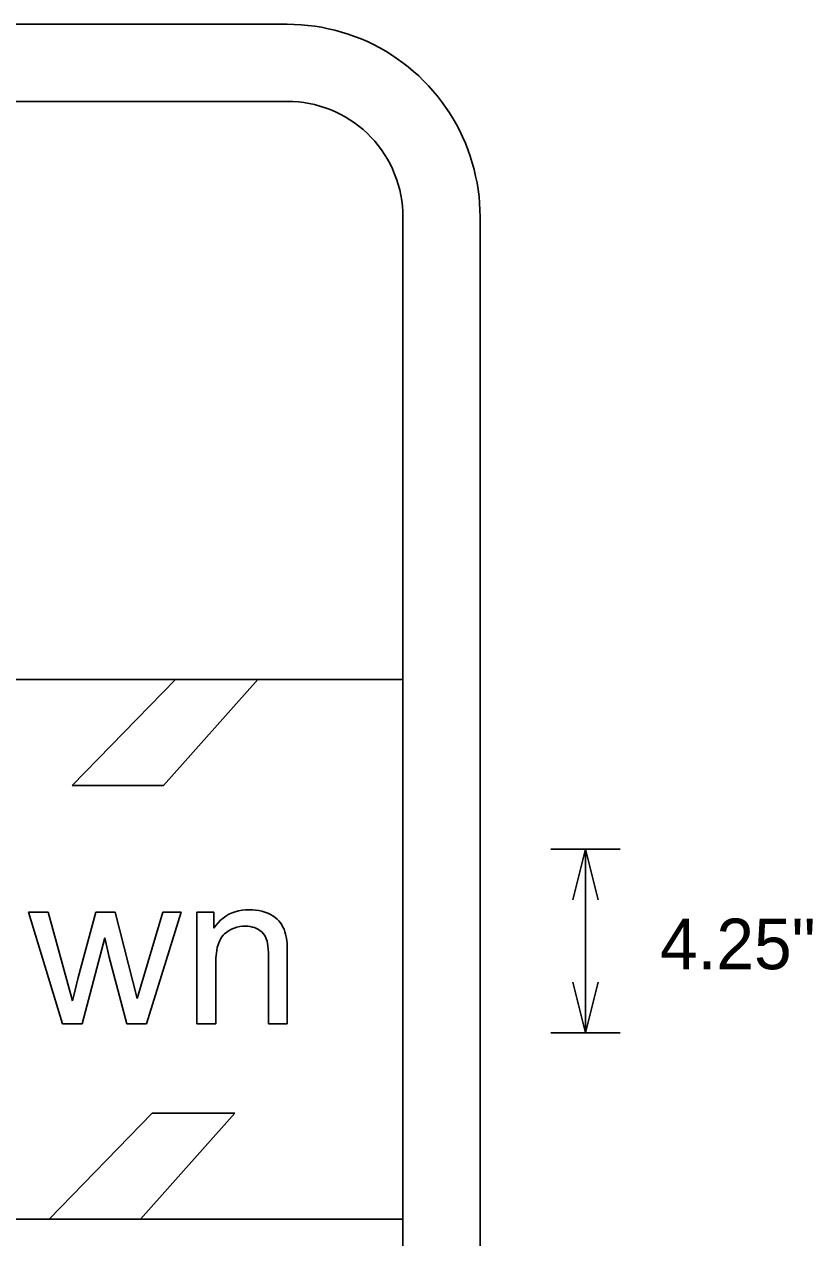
# Model space of a CAD drawing. Extents: x -2842 to 2681, y -2139 to 474.
# Drawn here: x 1523.1 to 1609.4, y -1691.3 to -1558.5 of the extents above; entities that cross this region are included whole.
import ezdxf

# ---------------------------------------------------------------- set-up
doc = ezdxf.new("R2010")
doc.units = 0
doc.layers.add('Default', color=7, linetype='Continuous')

msp = doc.modelspace()

# ---------------------------------------------------------------- linework, layer by layer
at = {"layer": 'Default'}
for p, q in [((1551.91, -1558.48), (1370.51, -1558.48)), ((1552.67, -1558.49), (1551.91, -1558.48)), ((1553.42, -1558.53), (1552.67, -1558.49)), ((1554.17, -1558.6), (1553.42, -1558.53)), ((1554.92, -1558.69), (1554.17, -1558.6)), ((1555.66, -1558.81), (1554.92, -1558.69)), ((1556.4, -1558.96), (1555.66, -1558.81)), ((1557.13, -1559.13), (1556.4, -1558.96)), ((1557.86, -1559.33), (1557.13, -1559.13)), ((1558.57, -1559.56), (1557.86, -1559.33)), ((1559.28, -1559.81), (1558.57, -1559.56)), ((1559.99, -1560.08), (1559.28, -1559.81)), ((1560.68, -1560.38), (1559.99, -1560.08)), ((1561.36, -1560.71), (1560.68, -1560.38)), ((1562.02, -1561.06), (1561.36, -1560.71)), ((1562.68, -1561.43), (1562.02, -1561.06)), ((1563.32, -1561.83), (1562.68, -1561.43)), ((1563.94, -1562.25), (1563.32, -1561.83)), ((1564.55, -1562.69), (1563.94, -1562.25)), ((1565.15, -1563.15), (1564.55, -1562.69)), ((1565.73, -1563.63), (1565.15, -1563.15)), ((1566.29, -1564.13), (1565.73, -1563.63)), ((1566.83, -1564.66), (1566.29, -1564.13)), ((1567.35, -1565.2), (1566.83, -1564.66)), ((1567.85, -1565.76), (1567.35, -1565.2)), ((1568.34, -1566.34), (1567.85, -1565.76)), ((1189.1, -1566.92), (1551.91, -1566.92)), ((1551.91, -1566.92), (1552.52, -1566.93)), ((1552.52, -1566.93), (1553.12, -1566.97)), ((1553.12, -1566.97), (1553.71, -1567.04)), ((1553.71, -1567.04), (1554.31, -1567.14)), ((1568.8, -1566.93), (1568.34, -1566.34)), ((1569.24, -1567.54), (1568.8, -1566.93)), ((1554.31, -1567.14), (1554.9, -1567.27)), ((1554.9, -1567.27), (1555.48, -1567.43)), ((1555.48, -1567.43), (1556.05, -1567.61)), ((1556.05, -1567.61), (1556.62, -1567.82)), ((1556.62, -1567.82), (1557.17, -1568.06)), ((1557.17, -1568.06), (1557.71, -1568.32)), ((1557.71, -1568.32), (1558.24, -1568.61)), ((1569.66, -1568.17), (1569.24, -1567.54)), ((1570.05, -1568.81), (1569.66, -1568.17)), ((1558.24, -1568.61), (1558.76, -1568.92)), ((1558.76, -1568.92), (1559.25, -1569.26)), ((1559.25, -1569.26), (1559.74, -1569.62)), ((1559.74, -1569.62), (1560.2, -1570.01)), ((1570.43, -1569.46), (1570.05, -1568.81)), ((1570.78, -1570.13), (1570.43, -1569.46)), ((1560.2, -1570.01), (1560.65, -1570.41)), ((1560.65, -1570.41), (1561.07, -1570.84)), ((1561.07, -1570.84), (1561.48, -1571.28)), ((1571.1, -1570.81), (1570.78, -1570.13)), ((1571.4, -1571.5), (1571.1, -1570.81)), ((1561.48, -1571.28), (1561.86, -1571.75)), ((1561.86, -1571.75), (1562.22, -1572.23)), ((1562.22, -1572.23), (1562.56, -1572.73)), ((1571.68, -1572.2), (1571.4, -1571.5)), ((1571.93, -1572.91), (1571.68, -1572.2)), ((1562.56, -1572.73), (1562.87, -1573.24)), ((1562.87, -1573.24), (1563.16, -1573.77)), ((1572.15, -1573.63), (1571.93, -1572.91)), ((1572.35, -1574.36), (1572.15, -1573.63)), ((1563.16, -1573.77), (1563.43, -1574.31)), ((1563.43, -1574.31), (1563.66, -1574.87)), ((1563.66, -1574.87), (1563.87, -1575.43)), ((1572.52, -1575.09), (1572.35, -1574.36)), ((1572.67, -1575.83), (1572.52, -1575.09)), ((1563.87, -1575.43), (1564.06, -1576.01)), ((1564.06, -1576.01), (1564.21, -1576.59)), ((1572.79, -1576.57), (1572.67, -1575.83)), ((1564.21, -1576.59), (1564.34, -1577.18)), ((1564.34, -1577.18), (1564.44, -1577.77)), ((1572.89, -1577.32), (1572.79, -1576.57)), ((1572.95, -1578.07), (1572.89, -1577.32)), ((1564.44, -1577.77), (1564.51, -1578.37)), ((1564.51, -1578.37), (1564.56, -1578.97)), ((1564.56, -1578.97), (1564.57, -1579.57)), ((1572.99, -1578.82), (1572.95, -1578.07)), ((1573.01, -1579.57), (1572.99, -1578.82)), ((1564.57, -1579.57), (1564.57, -1739.88)), ((1573.01, -1739.88), (1573.01, -1579.57)), ((1410.03, -1630.2), (1564.57, -1630.2)), ((1528.37, -1641.78), (1539.66, -1630.18)), ((1548.68, -1630.18), (1538.37, -1641.78)), ((1539.66, -1630.18), (1548.68, -1630.18)), ((1564.57, -1630.2), (1564.57, -1689.26)), ((1538.37, -1641.78), (1528.37, -1641.78)), ((1580.74, -1648.76), (1588.34, -1648.76)), ((1583.16, -1654.29), (1584.54, -1648.76)), ((1584.54, -1648.76), (1584.54, -1659.08)), ((1584.54, -1648.76), (1585.93, -1654.29)), ((1588.34, -1648.76), (1588.34, -1648.76)), ((1527.32, -1667.89), (1523.6, -1655.66)), ((1523.6, -1655.66), (1525.73, -1655.66)), ((1525.73, -1655.66), (1528.39, -1665.34)), ((1529.02, -1662.82), (1530.95, -1655.66)), ((1530.95, -1655.66), (1533.07, -1655.66)), ((1533.07, -1655.66), (1535.5, -1665.09)), ((1535.5, -1665.09), (1538.29, -1655.66)), ((1540.29, -1655.66), (1536.49, -1667.89)), ((1538.29, -1655.66), (1540.29, -1655.66)), ((1542.02, -1667.89), (1542.02, -1655.66)), ((1542.02, -1655.66), (1543.88, -1655.66)), ((1543.88, -1655.66), (1543.88, -1657.4)), ((1544.89, -1656.3), (1545.2, -1656.08)), ((1545.2, -1656.08), (1545.52, -1655.89)), ((1545.52, -1655.89), (1545.86, -1655.74)), ((1545.86, -1655.74), (1546.2, -1655.61)), ((1546.2, -1655.61), (1546.56, -1655.51)), ((1546.56, -1655.51), (1546.96, -1655.44)), ((1546.96, -1655.44), (1547.35, -1655.4)), ((1547.35, -1655.4), (1547.75, -1655.39)), ((1547.75, -1655.39), (1548.1, -1655.4)), ((1548.1, -1655.4), (1548.44, -1655.43)), ((1548.44, -1655.43), (1548.79, -1655.48)), ((1548.79, -1655.48), (1549.12, -1655.56)), ((1549.12, -1655.56), (1549.45, -1655.66)), ((1549.45, -1655.66), (1549.78, -1655.78)), ((1549.78, -1655.78), (1550.06, -1655.92)), ((1550.06, -1655.92), (1550.33, -1656.07)), ((1550.33, -1656.07), (1550.58, -1656.24)), ((1543.88, -1657.4), (1544.1, -1657.1)), ((1544.1, -1657.1), (1544.34, -1656.81)), ((1544.34, -1656.81), (1544.6, -1656.54)), ((1544.6, -1656.54), (1544.89, -1656.3)), ((1546.1, -1657.39), (1545.82, -1657.51)), ((1546.4, -1657.3), (1546.1, -1657.39)), ((1546.7, -1657.23), (1546.4, -1657.3)), ((1547.01, -1657.19), (1546.7, -1657.23)), ((1547.32, -1657.18), (1547.01, -1657.19)), ((1547.58, -1657.19), (1547.32, -1657.18)), ((1547.84, -1657.22), (1547.58, -1657.19)), ((1548.09, -1657.28), (1547.84, -1657.22)), ((1548.32, -1657.35), (1548.09, -1657.28)), ((1548.54, -1657.44), (1548.32, -1657.35)), ((1550.58, -1656.24), (1550.79, -1656.42)), ((1550.79, -1656.42), (1550.99, -1656.61)), ((1550.99, -1656.61), (1551.16, -1656.83)), ((1551.16, -1656.83), (1551.3, -1657.05)), ((1551.3, -1657.05), (1551.43, -1657.29)), ((1551.43, -1657.29), (1551.55, -1657.53)), ((1531.94, -1658.48), (1529.48, -1667.89)), ((1532.41, -1660.57), (1531.94, -1658.48)), ((1544.63, -1658.54), (1544.51, -1658.76)), ((1544.75, -1658.35), (1544.63, -1658.54)), ((1544.89, -1658.18), (1544.75, -1658.35)), ((1545.04, -1658.02), (1544.89, -1658.18)), ((1545.28, -1657.83), (1545.04, -1658.02)), ((1545.54, -1657.66), (1545.28, -1657.83)), ((1545.82, -1657.51), (1545.54, -1657.66)), ((1548.76, -1657.56), (1548.54, -1657.44)), ((1548.94, -1657.68), (1548.76, -1657.56)), ((1549.11, -1657.82), (1548.94, -1657.68)), ((1549.27, -1657.99), (1549.11, -1657.82)), ((1549.4, -1658.16), (1549.27, -1657.99)), ((1549.52, -1658.36), (1549.4, -1658.16)), ((1549.61, -1658.56), (1549.52, -1658.36)), ((1549.69, -1658.82), (1549.61, -1658.56)), ((1551.55, -1657.53), (1551.65, -1657.8)), ((1551.65, -1657.8), (1551.73, -1658.08)), ((1551.73, -1658.08), (1551.8, -1658.36)), ((1551.8, -1658.36), (1551.86, -1658.75)), ((1551.86, -1658.75), (1551.89, -1659.15)), ((1544.19, -1659.83), (1544.15, -1660.13)), ((1544.25, -1659.53), (1544.19, -1659.83)), ((1544.33, -1659.24), (1544.25, -1659.53)), ((1544.41, -1659), (1544.33, -1659.24)), ((1544.51, -1658.76), (1544.41, -1659)), ((1549.75, -1659.08), (1549.69, -1658.82)), ((1549.79, -1659.35), (1549.75, -1659.08)), ((1549.83, -1659.71), (1549.79, -1659.35)), ((1549.85, -1660.08), (1549.83, -1659.71)), ((1549.85, -1660.45), (1549.85, -1660.08)), ((1551.89, -1659.15), (1551.91, -1659.76)), ((1551.91, -1659.76), (1551.91, -1660.37)), ((1584.54, -1668.86), (1584.54, -1659.08)), ((1534.35, -1667.89), (1532.41, -1660.57)), ((1544.1, -1660.67), (1544.09, -1661.21)), ((1544.09, -1661.21), (1544.09, -1667.89)), ((1544.15, -1660.13), (1544.1, -1660.67)), ((1549.85, -1667.89), (1549.85, -1660.45)), ((1551.91, -1660.37), (1551.91, -1667.89)), ((1528.57, -1664.62), (1529.02, -1662.82)), ((1584.54, -1668.86), (1583.16, -1663.32)), ((1585.93, -1663.32), (1584.54, -1668.86)), ((1528.39, -1665.34), (1528.57, -1664.62)), ((1529.48, -1667.89), (1527.32, -1667.89)), ((1536.49, -1667.89), (1534.35, -1667.89)), ((1544.09, -1667.89), (1542.02, -1667.89)), ((1551.91, -1667.89), (1549.85, -1667.89)), ((1580.74, -1668.86), (1588.34, -1668.86)), ((1588.34, -1668.86), (1588.34, -1668.86)), ((1525.85, -1689.26), (1537.13, -1677.66)), ((1546.16, -1677.66), (1535.84, -1689.26)), ((1537.13, -1677.66), (1546.16, -1677.66)), ((1564.57, -1689.26), (1407.91, -1689.26)), ((1535.84, -1689.26), (1525.85, -1689.26))]:
    msp.add_line(p, q, dxfattribs=at)

# ---------------------------------------------------------------- texts
msp.add_text('4.25"', height=5.536, dxfattribs=at).set_placement((1592.69, -1661.9))

doc.saveas('drawing.dxf')
